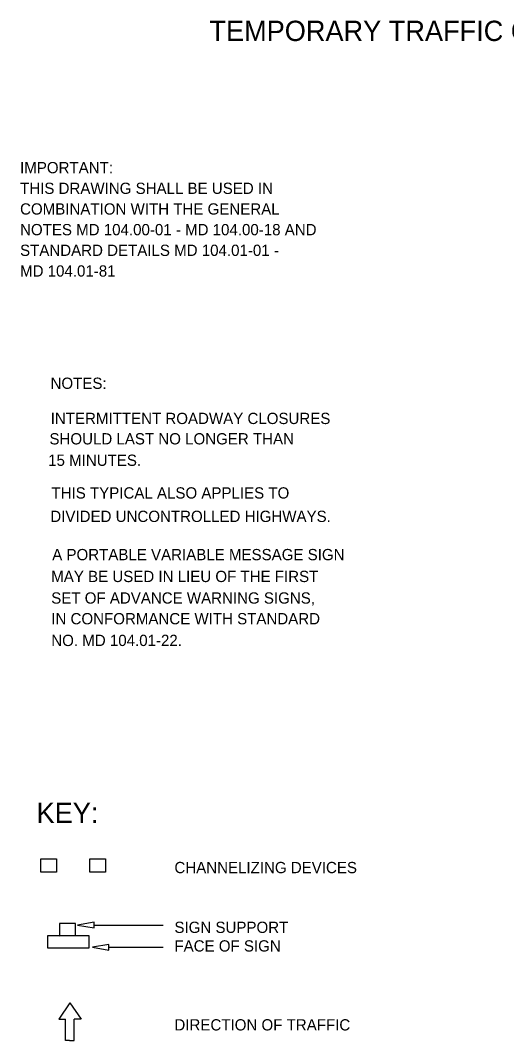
# Model space of a CAD drawing. Extents: x 1536.8 to 1543.6, y 1529.9 to 1539.9.
# Drawn here: x 1536.77 to 1539.36, y 1534.51 to 1539.94 of the extents above; entities that cross this region are included whole.
import ezdxf

# ---------------------------------------------------------------- set-up
doc = ezdxf.new("R2010")
doc.units = 0
for name, color, linetype in [('DETL-DIMS', 7, 'Continuous'), ('DETL-LINE', 7, 'Continuous'), ('DETL-NOTE', 7, 'Continuous'), ('DETL-TITL', 7, 'Continuous'), ('USER-BORD', 7, 'Continuous')]:
    doc.layers.add(name, color=color, linetype=linetype)

# ---------------------------------------------------------------- blocks, each defined once
blk = doc.blocks.new('DIR2')
at = {"layer": 'USER-BORD'}
for p, q in [((0, 0.0012), (-0.0342, -0.0477)), ((0, 0.0012), (0.0342, -0.0477)), ((-0.0342, -0.0477), (-0.0132, -0.0477)), ((-0.0132, -0.1133), (-0.0132, -0.0477)), ((0.0342, -0.0477), (0.0132, -0.0477)), ((0.0132, -0.1133), (0.0132, -0.0477)), ((-0.0011, -0.1133), (-0.0132, -0.1133)), ((-0.0011, -0.1133), (0.0011, -0.1133)), ((0.0011, -0.1133), (0.0132, -0.1133))]:
    blk.add_line(p, q, dxfattribs=at)
blk = doc.blocks.new('SIGN13')
at = {"layer": 'USER-BORD'}
for points in [[(-0.0134, 0.0182), (0.011, 0.0189), (0.011, 0.0371), (-0.0134, 0.0371)], [(-0.0314, 0.0182), (-0.0314, 0), (0.032, 0), (0.032, 0.0182)]]:
    blk.add_lwpolyline(points, close=True, dxfattribs=at)

msp = doc.modelspace()

# ---------------------------------------------------------------- linework, layer by layer
at = {"layer": 'DETL-DIMS'}
for p, q in [((1537.1654, 1535.1267), (1537.5324, 1535.1267)), ((1537.2438, 1535.0081), (1537.5324, 1535.0081))]:
    msp.add_line(p, q, dxfattribs=at)
for points in [[(1537.1654, 1535.1122), (1537.1654, 1535.1413), (1537.0778, 1535.1267)], [(1537.2438, 1534.9936), (1537.2438, 1535.0227), (1537.1562, 1535.0081)]]:
    msp.add_lwpolyline(points, close=True, dxfattribs=at)
at = {"layer": 'DETL-LINE'}
for points in [[(1536.8816, 1535.4082), (1536.8816, 1535.4788), (1536.9655, 1535.4788), (1536.9655, 1535.4082)], [(1537.1429, 1535.4082), (1537.1429, 1535.4788), (1537.2268, 1535.4788), (1537.2268, 1535.4082)]]:
    msp.add_lwpolyline(points, close=True, dxfattribs=at)

# ---------------------------------------------------------------- block references
for name, p, xscale, yscale in [('SIGN13', (1537.0277, 1535.0048), 3.5020038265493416, 3.502003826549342), ('DIR2', (1537.0372, 1534.71), 1.7510019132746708, 1.751001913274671)]:
    msp.add_blockref(name, p, dxfattribs=dict(at, xscale=xscale, yscale=yscale))

# ---------------------------------------------------------------- texts
at = {"layer": 'DETL-NOTE'}
for s, p in [('IMPORTANT:', (1536.7714, 1539.1284)), ('THIS DRAWING SHALL BE USED IN', (1536.7714, 1539.0184)), ('COMBINATION WITH THE GENERAL', (1536.7714, 1538.9084)), ('NOTES MD 104.00-01 - MD 104.00-18 AND', (1536.7714, 1538.7984)), ('STANDARD DETAILS MD 104.01-01 -', (1536.7714, 1538.6884)), ('MD 104.01-81', (1536.7714, 1538.5784)), ('NOTES:', (1536.9336, 1537.9807)), ('INTERMITTENT ROADWAY CLOSURES', (1536.9346, 1537.7935)), ('SHOULD LAST NO LONGER THAN', (1536.9279, 1537.685)), ('15 MINUTES.', (1536.921, 1537.5709)), ('THIS TYPICAL ALSO APPLIES TO ', (1536.9385, 1537.3969)), ('DIVIDED UNCONTROLLED HIGHWAYS.', (1536.9326, 1537.2722)), ('A PORTABLE VARIABLE MESSAGE SIGN ', (1536.9426, 1537.0686)), ('MAY BE USED IN LIEU OF THE FIRST', (1536.9373, 1536.9524)), ('SET OF ADVANCE WARNING SIGNS,', (1536.9373, 1536.8376)), ('IN CONFORMANCE WITH STANDARD', (1536.9376, 1536.7274)), ('NO. MD 104.01-22.', (1536.9376, 1536.6119)), ('CHANNELIZING DEVICES', (1537.5932, 1535.4028)), ('SIGN SUPPORT', (1537.5932, 1535.0846)), ('FACE OF SIGN', (1537.5932, 1534.9856)), ('DIRECTION OF TRAFFIC', (1537.5932, 1534.5655))]:
    msp.add_text(s, height=0.06, dxfattribs=at).set_placement(p)
at = {"layer": 'DETL-TITL'}
for s, p in [('TEMPORARY TRAFFIC CONTROL TYPICAL APPLICATION', (1537.7795, 1539.8325)), ('KEY:', (1536.8594, 1535.6696))]:
    msp.add_text(s, height=0.108, dxfattribs=at).set_placement(p)

doc.saveas('drawing.dxf')
